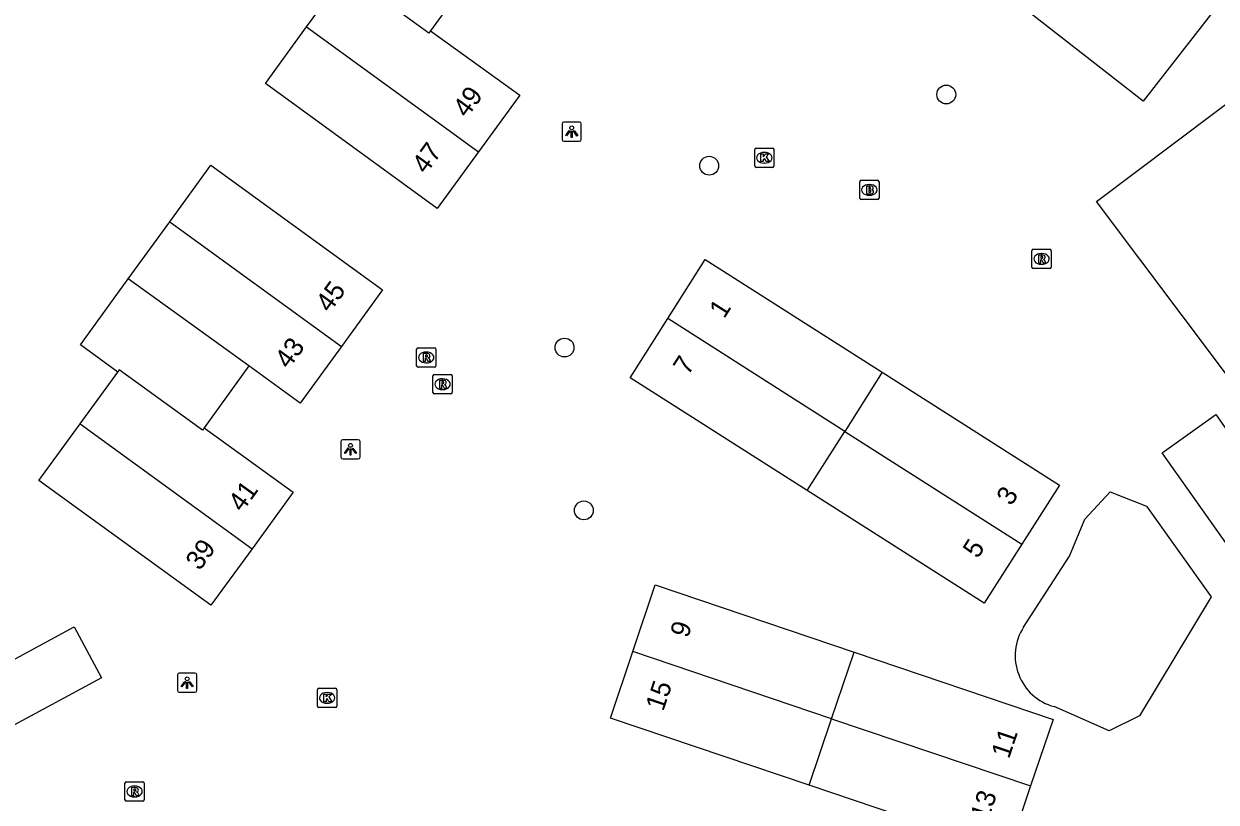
# Model space of a CAD drawing. Extents: x 159451 to 160663, y 388402 to 389723.
# Drawn here: x 159527.4 to 159589.3, y 389338.3 to 389378.7 of the extents above; entities that cross this region are included whole.
import ezdxf

# ---------------------------------------------------------------- set-up
doc = ezdxf.new("R2010")
doc.units = 0
for name, color, linetype in [('IMGEO_Boom', 7, 'Continuous'), ('IMGEO_Brandkraan', 7, 'Continuous'), ('IMGEO_Kolk', 7, 'Continuous'), ('IMGEO_Lichtpunt', 7, 'Continuous'), ('IMGEO_Meer_plas_ven_vijver', 7, 'Continuous'), ('IMGEO_Pand', 7, 'Continuous'), ('IMGEO_Pand_nummerreeks', 7, 'Continuous'), ('IMGEO_Rijbaan_lokaal_gesloten', 7, 'Continuous'), ('IMGEO_Rioolput', 7, 'Continuous')]:
    doc.layers.add(name, color=color, linetype=linetype)

msp = doc.modelspace()

# ---------------------------------------------------------------- linework, layer by layer
at = {"layer": 'IMGEO_Boom'}
for centre in [(159575.267, 389374.993), (159562.961, 389371.299), (159555.454, 389361.859), (159556.455, 389353.409)]:
    msp.add_circle(centre, 0.489, dxfattribs=at)
at = {"layer": 'IMGEO_Brandkraan'}
for p, q in [((159570.773, 389369.615), (159570.773, 389370.467)), ((159570.848, 389370.541), (159571.7, 389370.541)), ((159571.774, 389370.467), (159571.774, 389369.615)), ((159571.261, 389370.321), (159571.286, 389370.321)), ((159571.7, 389369.541), (159570.848, 389369.541)), ((159571.284, 389369.761), (159571.259, 389369.761))]:
    msp.add_line(p, q, dxfattribs=at)
for points in [[(159570.773, 389369.615), (159570.773, 389370.467)], [(159570.848, 389370.541), (159571.7, 389370.541)], [(159571.774, 389370.467), (159571.774, 389369.615)], [(159571.121, 389370.241), (159571.121, 389369.841), (159571.334, 389369.841)], [(159571.352, 389370.241), (159571.121, 389370.241)], [(159571.3, 389370.16), (159571.246, 389370.16), (159571.246, 389370.084)], [(159571.246, 389370.084), (159571.299, 389370.084)], [(159571.308, 389370.008), (159571.246, 389370.008), (159571.246, 389369.927)], [(159571.246, 389369.927), (159571.308, 389369.927)], [(159571.7, 389369.541), (159570.848, 389369.541)]]:
    msp.add_lwpolyline(points, dxfattribs=at)
for centre, radius, start, end in [((159570.85, 389370.465), 0.0765, 91.55205, 178.44795), ((159570.85, 389370.465), 0.0765, 91.55205, 178.44795), ((159571.698, 389370.465), 0.0765, 1.55205, 88.44795), ((159571.698, 389370.465), 0.0765, 1.55205, 88.44795), ((159571.301, 389370.122), 0.0379, 267.82845, 90.93552), ((159571.309, 389369.967), 0.0404, 269.87594, 90.50774), ((159571.34, 389370.092), 0.251, 268.66757, 293.53466), ((159571.356, 389370.096), 0.145, 59.4692, 91.53667), ((159571.381, 389370.143), 0.0922, 285.51372, 58.15012), ((159571.386, 389369.951), 0.105, 301.31148, 78.98903), ((159570.85, 389369.617), 0.0765, 181.55205, 268.44795), ((159570.85, 389369.617), 0.0765, 181.55205, 268.44795), ((159571.698, 389369.617), 0.0765, 271.55205, 358.44795), ((159571.698, 389369.617), 0.0765, 271.55205, 358.44795)]:
    msp.add_arc(centre, radius, start, end, dxfattribs=at)
for centre, major_axis, ratio, start_param, end_param in [((159571.26, 389370.041), (-0.387, 0.002), 0.722429, 4.712389, 7.853982), ((159571.285, 389370.041), (-0.39, 0.002), 0.717154, 1.570796, 4.712389)]:
    msp.add_ellipse(centre, major_axis=major_axis, ratio=ratio, start_param=start_param, end_param=end_param, dxfattribs=at)
at = {"layer": 'IMGEO_Kolk'}
for p, q in [((159565.323, 389371.283), (159565.323, 389372.135)), ((159565.398, 389372.209), (159566.25, 389372.209)), ((159565.811, 389371.989), (159565.836, 389371.989)), ((159566.324, 389372.135), (159566.324, 389371.283)), ((159566.25, 389371.209), (159565.398, 389371.209)), ((159565.834, 389371.429), (159565.809, 389371.429)), ((159542.632, 389343.252), (159542.632, 389344.104)), ((159542.707, 389344.178), (159543.559, 389344.178)), ((159543.12, 389343.958), (159543.145, 389343.958)), ((159543.633, 389344.104), (159543.633, 389343.252)), ((159543.559, 389343.178), (159542.707, 389343.178)), ((159543.143, 389343.398), (159543.118, 389343.398))]:
    msp.add_line(p, q, dxfattribs=at)
for points in [[(159565.323, 389371.283), (159565.323, 389372.135)], [(159565.398, 389372.209), (159566.25, 389372.209)], [(159565.644, 389371.909), (159565.767, 389371.909), (159565.767, 389371.758), (159565.897, 389371.909), (159566.061, 389371.909), (159565.915, 389371.758), (159566.068, 389371.509), (159565.916, 389371.509), (159565.831, 389371.673), (159565.767, 389371.606), (159565.767, 389371.509), (159565.644, 389371.509), (159565.644, 389371.909)], [(159566.324, 389372.135), (159566.324, 389371.283)], [(159566.25, 389371.209), (159565.398, 389371.209)], [(159542.632, 389343.252), (159542.632, 389344.104)], [(159542.707, 389344.178), (159543.559, 389344.178)], [(159542.953, 389343.878), (159543.076, 389343.878), (159543.076, 389343.727), (159543.206, 389343.878), (159543.37, 389343.878), (159543.224, 389343.727), (159543.377, 389343.478), (159543.225, 389343.478), (159543.14, 389343.642), (159543.076, 389343.575), (159543.076, 389343.478), (159542.953, 389343.478), (159542.953, 389343.878)], [(159543.633, 389344.104), (159543.633, 389343.252)], [(159543.559, 389343.178), (159542.707, 389343.178)]]:
    msp.add_lwpolyline(points, dxfattribs=at)
for centre, start, end in [((159565.4, 389372.133), 91.55205, 178.44795), ((159565.4, 389372.133), 91.55205, 178.44795), ((159566.248, 389372.133), 1.55205, 88.44795), ((159566.248, 389372.133), 1.55205, 88.44795), ((159565.4, 389371.285), 181.55205, 268.44795), ((159565.4, 389371.285), 181.55205, 268.44795), ((159566.248, 389371.285), 271.55205, 358.44795), ((159566.248, 389371.285), 271.55205, 358.44795), ((159542.709, 389344.102), 91.55205, 178.44795), ((159542.709, 389344.102), 91.55205, 178.44795), ((159543.557, 389344.102), 1.55205, 88.44795), ((159543.557, 389344.102), 1.55205, 88.44795), ((159542.709, 389343.254), 181.55205, 268.44795), ((159542.709, 389343.254), 181.55205, 268.44795), ((159543.557, 389343.254), 271.55205, 358.44795), ((159543.557, 389343.254), 271.55205, 358.44795)]:
    msp.add_arc(centre, 0.0765, start, end, dxfattribs=at)
for centre, major_axis, ratio, start_param, end_param in [((159565.81, 389371.709), (-0.387, 0.002), 0.722429, 4.712389, 7.853982), ((159565.835, 389371.709), (-0.39, 0.002), 0.717154, 1.570796, 4.712389), ((159543.119, 389343.678), (-0.387, 0.002), 0.722429, 4.712389, 7.853982), ((159543.144, 389343.678), (-0.39, 0.002), 0.717154, 1.570796, 4.712389)]:
    msp.add_ellipse(centre, major_axis=major_axis, ratio=ratio, start_param=start_param, end_param=end_param, dxfattribs=at)
at = {"layer": 'IMGEO_Lichtpunt'}
for p, q in [((159556.23, 389373.561), (159555.422, 389373.561)), ((159556.23, 389373.561), (159555.422, 389373.561)), ((159555.328, 389373.466), (159555.328, 389372.659)), ((159555.328, 389373.466), (159555.328, 389372.659)), ((159556.324, 389372.659), (159556.324, 389373.466)), ((159556.324, 389372.659), (159556.324, 389373.466)), ((159555.422, 389372.565), (159556.23, 389372.565)), ((159555.422, 389372.565), (159556.23, 389372.565)), ((159543.847, 389356.984), (159543.847, 389356.177)), ((159543.847, 389356.984), (159543.847, 389356.177)), ((159544.749, 389357.079), (159543.941, 389357.079)), ((159544.749, 389357.079), (159543.941, 389357.079)), ((159544.843, 389356.177), (159544.843, 389356.984)), ((159544.843, 389356.177), (159544.843, 389356.984)), ((159543.941, 389356.083), (159544.749, 389356.083)), ((159543.941, 389356.083), (159544.749, 389356.083)), ((159535.366, 389344.873), (159535.366, 389344.066)), ((159535.366, 389344.873), (159535.366, 389344.066)), ((159536.268, 389344.968), (159535.46, 389344.968)), ((159536.268, 389344.968), (159535.46, 389344.968)), ((159536.362, 389344.066), (159536.362, 389344.873)), ((159536.362, 389344.066), (159536.362, 389344.873)), ((159535.46, 389343.972), (159536.268, 389343.972)), ((159535.46, 389343.972), (159536.268, 389343.972))]:
    msp.add_line(p, q, dxfattribs=at)
for points in [[(159555.702, 389373.13), (159555.741, 389373.102), (159555.553, 389372.84), (159555.515, 389372.867), (159555.702, 389373.13)], [(159555.804, 389373.082), (159555.851, 389373.082), (159555.851, 389372.76), (159555.804, 389372.76), (159555.804, 389373.082)], [(159555.914, 389373.102), (159555.952, 389373.129), (159556.139, 389372.867), (159556.1, 389372.839), (159555.914, 389373.102)], [(159544.221, 389356.648), (159544.26, 389356.62), (159544.072, 389356.358), (159544.034, 389356.385), (159544.221, 389356.648)], [(159544.323, 389356.6), (159544.37, 389356.6), (159544.37, 389356.278), (159544.323, 389356.278), (159544.323, 389356.6)], [(159544.433, 389356.62), (159544.471, 389356.647), (159544.658, 389356.385), (159544.619, 389356.357), (159544.433, 389356.62)], [(159535.74, 389344.537), (159535.779, 389344.509), (159535.591, 389344.247), (159535.553, 389344.274), (159535.74, 389344.537)], [(159535.842, 389344.489), (159535.889, 389344.489), (159535.889, 389344.167), (159535.842, 389344.167), (159535.842, 389344.489)], [(159535.952, 389344.509), (159535.99, 389344.536), (159536.177, 389344.274), (159536.138, 389344.246), (159535.952, 389344.509)]]:
    msp.add_lwpolyline(points, dxfattribs=at)
for centre in [(159555.827, 389373.264), (159544.346, 389356.782), (159535.865, 389344.671)]:
    msp.add_circle(centre, 0.0994, dxfattribs=at)
for centre, start, end in [((159555.422, 389373.466), 90, 180), ((159555.422, 389373.466), 90, 180), ((159556.23, 389373.466), 0, 90), ((159556.23, 389373.466), 0, 90), ((159555.422, 389372.659), 180, 270), ((159555.422, 389372.659), 180, 270), ((159556.23, 389372.659), 270, 0), ((159556.23, 389372.659), 270, 360), ((159543.941, 389356.984), 90, 180), ((159543.941, 389356.984), 90, 180), ((159544.749, 389356.984), 0, 90), ((159544.749, 389356.984), 0, 90), ((159543.941, 389356.177), 180, 270), ((159543.941, 389356.177), 180, 270), ((159544.749, 389356.177), 270, 0), ((159544.749, 389356.177), 270, 360), ((159535.46, 389344.873), 90, 180), ((159535.46, 389344.873), 90, 180), ((159536.268, 389344.873), 0, 90), ((159536.268, 389344.873), 0, 90), ((159535.46, 389344.066), 180, 270), ((159535.46, 389344.066), 180, 270), ((159536.268, 389344.066), 270, 0), ((159536.268, 389344.066), 270, 360)]:
    msp.add_arc(centre, 0.0946, start, end, dxfattribs=at)
at = {"layer": 'IMGEO_Meer_plas_ven_vijver'}
for points in [[(159579.281, 389347.357), (159581.666, 389351.038), (159582.45, 389352.959), (159583.776, 389354.373), (159585.651, 389353.634), (159589.012, 389348.926)], [(159589.012, 389348.926), (159585.291, 389342.745), (159583.718, 389341.973), (159580.859, 389343.226)]]:
    msp.add_lwpolyline(points, dxfattribs=at)
msp.add_arc((159581.582, 389345.869), 2.74, 147.10719, 254.70551, dxfattribs=at)
at = {"layer": 'IMGEO_Pand'}
for points in [[(159585.487, 389374.644), (159576.692, 389381.52), (159598.547, 389409.538), (159607.34, 389402.676), (159585.487, 389374.644)], [(159589.76, 389360.534), (159583.054, 389369.444), (159605.812, 389386.575), (159612.526, 389377.663), (159589.76, 389360.534)], [(159542.07, 389378.502), (159544.025, 389381.192)], [(159548.499, 389378.301), (159548.409, 389378.178), (159544.107, 389381.305), (159544.025, 389381.192)], [(159550.822, 389381.5), (159548.499, 389378.301)], [(159550.988, 389372.017), (159548.85, 389369.078), (159539.931, 389375.559), (159542.07, 389378.502)], [(159542.07, 389378.502), (159550.988, 389372.017)], [(159548.499, 389378.301), (159553.125, 389374.956), (159550.988, 389372.017)], [(159534.968, 389368.393), (159537.093, 389371.322), (159546.012, 389364.851), (159543.877, 389361.915)], [(159532.812, 389365.422), (159534.968, 389368.393)], [(159534.968, 389368.393), (159543.877, 389361.915)], [(159560.807, 389363.367), (159562.752, 389366.429), (159571.944, 389360.576)], [(159532.266, 389360.591), (159530.328, 389361.998), (159532.812, 389365.422)], [(159539.068, 389360.907), (159532.812, 389365.422)], [(159568.038, 389354.442), (159558.855, 389360.293), (159560.807, 389363.367)], [(159569.993, 389357.512), (159560.807, 389363.367)], [(159543.877, 389361.915), (159541.741, 389358.978), (159539.068, 389360.907)], [(159530.316, 389357.903), (159532.266, 389360.591)], [(159536.75, 389357.697), (159536.664, 389357.578), (159532.344, 389360.698), (159532.266, 389360.591)], [(159539.068, 389360.907), (159536.75, 389357.697)], [(159571.944, 389360.576), (159569.993, 389357.512)], [(159571.944, 389360.576), (159581.136, 389354.724), (159579.181, 389351.657)], [(159539.233, 389351.422), (159537.096, 389348.482), (159528.176, 389354.954), (159530.316, 389357.903)], [(159530.316, 389357.903), (159539.233, 389351.422)], [(159536.75, 389357.697), (159541.37, 389354.362), (159539.233, 389351.422)], [(159568.038, 389354.442), (159569.993, 389357.512)], [(159569.993, 389357.512), (159579.181, 389351.657)], [(159579.181, 389351.657), (159577.226, 389348.589), (159568.038, 389354.442)], [(159558.992, 389346.082), (159560.158, 389349.546), (159570.482, 389346.054)], [(159531.423, 389344.725), (159522.948, 389340.15), (159521.508, 389342.76), (159530.004, 389347.358), (159531.423, 389344.725)], [(159568.144, 389339.143), (159557.83, 389342.632), (159558.992, 389346.082)], [(159569.312, 389342.595), (159558.992, 389346.082)], [(159569.312, 389342.595), (159570.482, 389346.054)], [(159570.482, 389346.054), (159580.805, 389342.563), (159579.637, 389339.107)], [(159568.144, 389339.143), (159569.312, 389342.595)], [(159569.312, 389342.595), (159579.637, 389339.107)], [(159579.637, 389339.107), (159578.47, 389335.651), (159568.144, 389339.143)]]:
    msp.add_lwpolyline(points, dxfattribs=at)
at = {"layer": 'IMGEO_Rijbaan_lokaal_gesloten'}
msp.add_lwpolyline([(159591.074, 389349.897), (159586.47, 389356.404), (159589.258, 389358.394), (159593.822, 389351.872), (159593.097, 389351.323)], dxfattribs=at)
at = {"layer": 'IMGEO_Rioolput'}
for p, q in [((159579.707, 389366.033), (159579.707, 389366.885)), ((159579.782, 389366.959), (159580.634, 389366.959)), ((159580.195, 389366.739), (159580.22, 389366.739)), ((159580.708, 389366.885), (159580.708, 389366.033)), ((159580.218, 389366.179), (159580.193, 389366.179)), ((159580.634, 389365.959), (159579.782, 389365.959)), ((159547.775, 389360.92), (159547.775, 389361.772)), ((159547.85, 389361.846), (159548.702, 389361.846)), ((159548.776, 389361.772), (159548.776, 389360.92)), ((159548.263, 389361.626), (159548.288, 389361.626)), ((159548.702, 389360.846), (159547.85, 389360.846)), ((159548.286, 389361.066), (159548.261, 389361.066)), ((159548.621, 389359.532), (159548.621, 389360.384)), ((159548.696, 389360.458), (159549.548, 389360.458)), ((159549.109, 389360.238), (159549.134, 389360.238)), ((159549.622, 389360.384), (159549.622, 389359.532)), ((159549.548, 389359.458), (159548.696, 389359.458)), ((159549.132, 389359.678), (159549.107, 389359.678)), ((159532.639, 389338.395), (159532.639, 389339.247)), ((159532.714, 389339.321), (159533.566, 389339.321)), ((159533.127, 389339.101), (159533.152, 389339.101)), ((159533.64, 389339.247), (159533.64, 389338.395)), ((159533.566, 389338.321), (159532.714, 389338.321)), ((159533.15, 389338.541), (159533.125, 389338.541))]:
    msp.add_line(p, q, dxfattribs=at)
for points in [[(159579.707, 389366.033), (159579.707, 389366.885)], [(159579.782, 389366.959), (159580.634, 389366.959)], [(159580.708, 389366.885), (159580.708, 389366.033)], [(159580.296, 389366.657), (159580.044, 389366.659), (159580.044, 389366.259)], [(159580.044, 389366.259), (159580.168, 389366.259), (159580.168, 389366.421), (159580.179, 389366.421)], [(159580.222, 389366.578), (159580.168, 389366.578), (159580.168, 389366.497)], [(159580.168, 389366.497), (159580.22, 389366.497)], [(159580.226, 389366.392), (159580.297, 389366.259), (159580.437, 389366.259), (159580.372, 389366.385)], [(159580.634, 389365.959), (159579.782, 389365.959)], [(159547.775, 389360.92), (159547.775, 389361.772)], [(159547.85, 389361.846), (159548.702, 389361.846)], [(159548.776, 389361.772), (159548.776, 389360.92)], [(159548.364, 389361.544), (159548.112, 389361.546), (159548.112, 389361.146)], [(159548.112, 389361.146), (159548.236, 389361.146), (159548.236, 389361.308), (159548.247, 389361.308)], [(159548.29, 389361.465), (159548.236, 389361.465), (159548.236, 389361.384)], [(159548.236, 389361.384), (159548.288, 389361.384)], [(159548.294, 389361.279), (159548.365, 389361.146), (159548.505, 389361.146), (159548.44, 389361.272)], [(159548.702, 389360.846), (159547.85, 389360.846)], [(159548.621, 389359.532), (159548.621, 389360.384)], [(159548.696, 389360.458), (159549.548, 389360.458)], [(159549.21, 389360.156), (159548.958, 389360.158), (159548.958, 389359.758)], [(159548.958, 389359.758), (159549.082, 389359.758), (159549.082, 389359.92), (159549.093, 389359.92)], [(159549.136, 389360.077), (159549.082, 389360.077), (159549.082, 389359.996)], [(159549.082, 389359.996), (159549.134, 389359.996)], [(159549.14, 389359.891), (159549.211, 389359.758), (159549.351, 389359.758), (159549.286, 389359.884)], [(159549.622, 389360.384), (159549.622, 389359.532)], [(159549.548, 389359.458), (159548.696, 389359.458)], [(159532.639, 389338.395), (159532.639, 389339.247)], [(159532.714, 389339.321), (159533.566, 389339.321)], [(159533.228, 389339.019), (159532.976, 389339.021), (159532.976, 389338.621)], [(159533.154, 389338.94), (159533.1, 389338.94), (159533.1, 389338.859)], [(159533.1, 389338.859), (159533.152, 389338.859)], [(159533.64, 389339.247), (159533.64, 389338.395)], [(159533.566, 389338.321), (159532.714, 389338.321)], [(159532.976, 389338.621), (159533.1, 389338.621), (159533.1, 389338.783), (159533.111, 389338.783)], [(159533.158, 389338.754), (159533.229, 389338.621), (159533.369, 389338.621), (159533.304, 389338.747)]]:
    msp.add_lwpolyline(points, dxfattribs=at)
for centre, radius, start, end in [((159579.784, 389366.883), 0.0765, 91.55205, 178.44795), ((159579.784, 389366.883), 0.0765, 91.55205, 178.44795), ((159580.632, 389366.883), 0.0765, 1.55205, 88.44795), ((159580.632, 389366.883), 0.0765, 1.55205, 88.44795), ((159580.178, 389366.368), 0.0533, 26.02933, 88.69889), ((159580.204, 389366.686), 0.19, 274.7715, 282.96867), ((159580.228, 389366.482), 0.0964, 77.00612, 93.18647), ((159580.242, 389366.539), 0.0378, 276.66336, 79.67722), ((159580.295, 389366.547), 0.109, 350.36119, 89.41601), ((159580.293, 389366.547), 0.112, 277.58423, 350.98172), ((159580.277, 389366.332), 0.108, 29.51342, 73.79051), ((159579.784, 389366.035), 0.0765, 181.55205, 268.44795), ((159579.784, 389366.035), 0.0765, 181.55205, 268.44795), ((159580.632, 389366.035), 0.0765, 271.55205, 358.44795), ((159580.632, 389366.035), 0.0765, 271.55205, 358.44795), ((159547.852, 389361.77), 0.0765, 91.55205, 178.44795), ((159547.852, 389361.77), 0.0765, 91.55205, 178.44795), ((159548.7, 389361.77), 0.0765, 1.55205, 88.44795), ((159548.7, 389361.77), 0.0765, 1.55205, 88.44795), ((159548.246, 389361.255), 0.0533, 26.02933, 88.69889), ((159548.272, 389361.573), 0.19, 274.7715, 282.96867), ((159548.296, 389361.369), 0.0964, 77.00612, 93.18647), ((159548.31, 389361.426), 0.0378, 276.66336, 79.67722), ((159548.363, 389361.434), 0.109, 350.36119, 89.41601), ((159548.361, 389361.434), 0.112, 277.58423, 350.98172), ((159548.345, 389361.219), 0.108, 29.51342, 73.79051), ((159547.852, 389360.922), 0.0765, 181.55205, 268.44795), ((159547.852, 389360.922), 0.0765, 181.55205, 268.44795), ((159548.7, 389360.922), 0.0765, 271.55205, 358.44795), ((159548.7, 389360.922), 0.0765, 271.55205, 358.44795), ((159548.698, 389360.382), 0.0765, 91.55205, 178.44795), ((159548.698, 389360.382), 0.0765, 91.55205, 178.44795), ((159549.092, 389359.867), 0.0533, 26.02933, 88.69889), ((159549.118, 389360.185), 0.19, 274.7715, 282.96867), ((159549.142, 389359.981), 0.0964, 77.00612, 93.18647), ((159549.156, 389360.038), 0.0378, 276.66336, 79.67722), ((159549.209, 389360.046), 0.109, 350.36119, 89.41601), ((159549.207, 389360.046), 0.112, 277.58423, 350.98172), ((159549.191, 389359.831), 0.108, 29.51342, 73.79051), ((159549.546, 389360.382), 0.0765, 1.55205, 88.44795), ((159549.546, 389360.382), 0.0765, 1.55205, 88.44795), ((159548.698, 389359.534), 0.0765, 181.55205, 268.44795), ((159548.698, 389359.534), 0.0765, 181.55205, 268.44795), ((159549.546, 389359.534), 0.0765, 271.55205, 358.44795), ((159549.546, 389359.534), 0.0765, 271.55205, 358.44795), ((159532.716, 389339.245), 0.0765, 91.55205, 178.44795), ((159532.716, 389339.245), 0.0765, 91.55205, 178.44795), ((159533.136, 389339.048), 0.19, 274.7715, 282.96867), ((159533.16, 389338.844), 0.0964, 77.00612, 93.18647), ((159533.174, 389338.901), 0.0378, 276.66336, 79.67722), ((159533.227, 389338.909), 0.109, 350.36119, 89.41601), ((159533.225, 389338.909), 0.112, 277.58423, 350.98172), ((159533.564, 389339.245), 0.0765, 1.55205, 88.44795), ((159533.564, 389339.245), 0.0765, 1.55205, 88.44795), ((159532.716, 389338.397), 0.0765, 181.55205, 268.44795), ((159532.716, 389338.397), 0.0765, 181.55205, 268.44795), ((159533.11, 389338.73), 0.0533, 26.02933, 88.69889), ((159533.209, 389338.694), 0.108, 29.51342, 73.79051), ((159533.564, 389338.397), 0.0765, 271.55205, 358.44795), ((159533.564, 389338.397), 0.0765, 271.55205, 358.44795)]:
    msp.add_arc(centre, radius, start, end, dxfattribs=at)
for centre, major_axis, ratio, start_param, end_param in [((159580.194, 389366.459), (-0.387, 0.002), 0.722429, 4.712389, 7.853982), ((159580.219, 389366.459), (-0.39, 0.002), 0.717154, 1.570796, 4.712389), ((159548.262, 389361.346), (-0.387, 0.002), 0.722429, 4.712389, 7.853982), ((159548.287, 389361.346), (-0.39, 0.002), 0.717154, 1.570796, 4.712389), ((159549.108, 389359.958), (-0.387, 0.002), 0.722429, 4.712389, 7.853982), ((159549.133, 389359.958), (-0.39, 0.002), 0.717154, 1.570796, 4.712389), ((159533.126, 389338.821), (-0.387, 0.002), 0.722429, 4.712389, 7.853982), ((159533.151, 389338.821), (-0.39, 0.002), 0.717154, 1.570796, 4.712389)]:
    msp.add_ellipse(centre, major_axis=major_axis, ratio=ratio, start_param=start_param, end_param=end_param, dxfattribs=at)

# ---------------------------------------------------------------- texts
at = {"layer": 'IMGEO_Pand_nummerreeks'}
for s, rotation, p in [('49', 53.97262, (159550.385, 389373.739)), ('47', 53.97262, (159548.26, 389370.817)), ('45', 53.97262, (159543.266, 389363.625)), ('1', 57.58226, (159563.738, 389363.32)), ('43', 53.97262, (159541.139, 389360.701)), ('7', 57.58226, (159561.869, 389360.376)), ('41', 53.98981, (159538.725, 389353.273)), ('3', 57.49059, (159578.643, 389353.602)), ('39', 53.98981, (159536.52, 389350.24)), ('5', 57.49059, (159576.9, 389350.867)), ('9', 71.39054, (159561.851, 389346.743)), ('15', 71.39054, (159560.574, 389342.946)), ('11', 71.33325, (159578.517, 389340.478)), ('13', 71.33325, (159577.429, 389337.254))]:
    msp.add_text(s, height=1, rotation=rotation, dxfattribs=at).set_placement(p)

doc.saveas('drawing.dxf')
